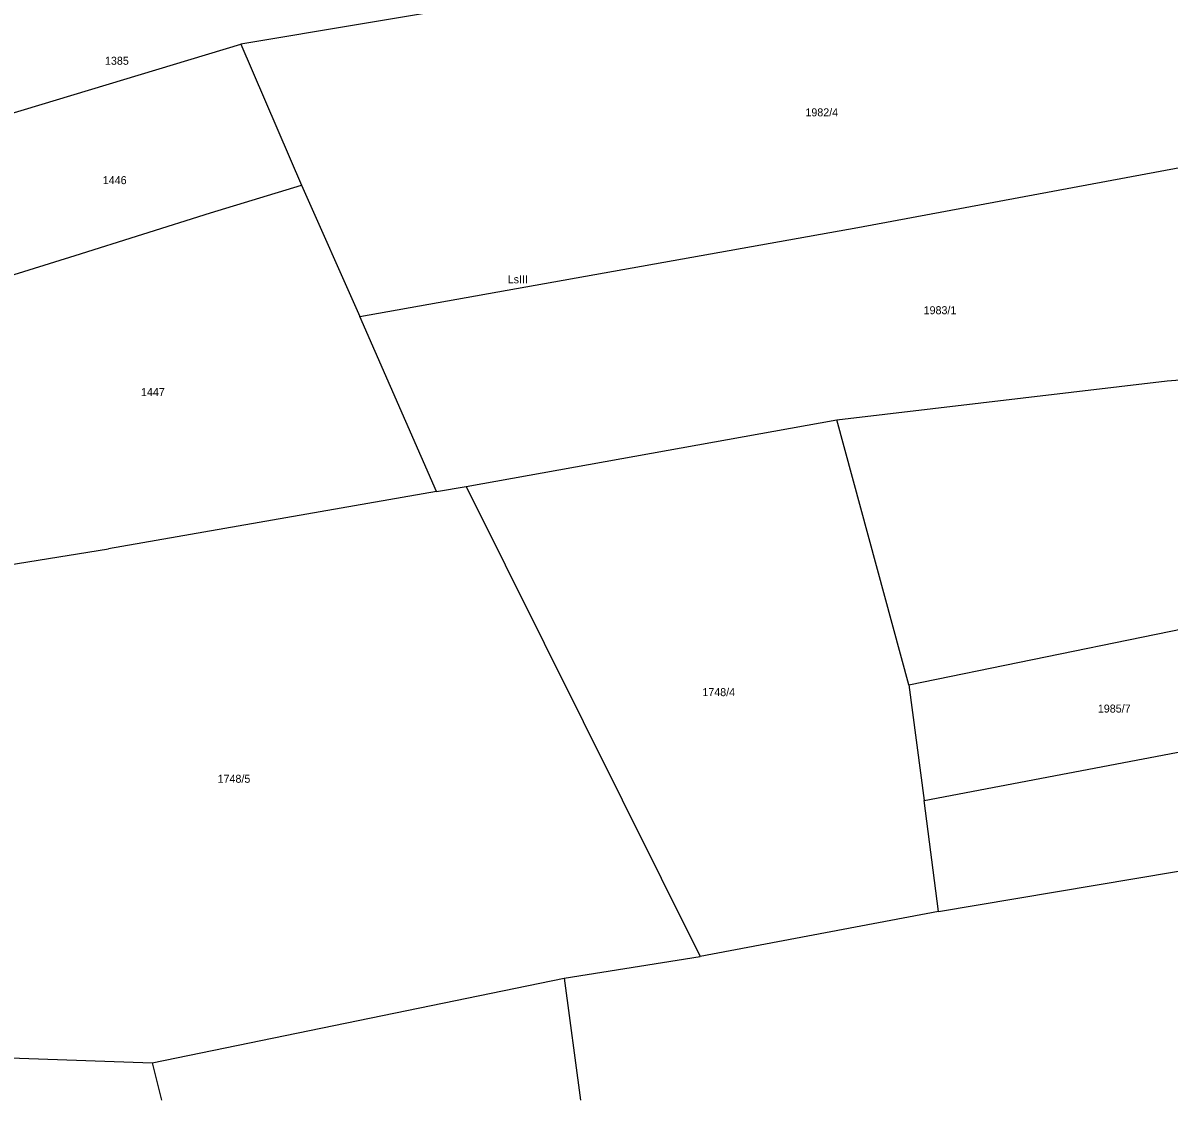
# Model space of a CAD drawing. Extents: x 7498273 to 7499989, y 5499795 to 5500810.
# Drawn here: x 7498679 to 7498893.9, y 5499795 to 5499997 of the extents above; entities that cross this region are included whole.
import ezdxf

# ---------------------------------------------------------------- set-up
doc = ezdxf.new("R2010")
doc.units = 0
for name, color, linetype in [('209-oznaczenie konturu klasyfikacyjnego', 7, 'Continuous'), ('211-numer działki ewidencyjnej', 7, 'Continuous'), ('219-działka ewidencyjna', 7, 'Continuous')]:
    doc.layers.add(name, color=color, linetype=linetype)

msp = doc.modelspace()

# ---------------------------------------------------------------- linework, layer by layer
at = {"layer": '219-działka ewidencyjna'}
for points in [[(7498788.28, 5500004.48), (7498719.91, 5499992.98)], [(7498663.32, 5499975.91), (7498719.91, 5499992.98)], [(7498719.91, 5499992.98), (7498731.28, 5499966.57)], [(7498835.55, 5499958.63), (7498922.42, 5499974.79)], [(7498714.17, 5499961.38), (7498731.28, 5499966.57)], [(7498731.28, 5499966.57), (7498742.22, 5499941.9)], [(7498688.82, 5499953.39), (7498714.17, 5499961.38)], [(7498742.22, 5499941.9), (7498835.55, 5499958.63)], [(7498671.54, 5499948.01), (7498688.82, 5499953.39)], [(7498756.55, 5499909.13), (7498742.22, 5499941.9)], [(7498893.51, 5499929.87), (7498953.54, 5499934.44)], [(7498831.64, 5499922.58), (7498893.51, 5499929.87)], [(7498762.13, 5499910.03), (7498831.64, 5499922.58)], [(7498845.11, 5499872.88), (7498831.64, 5499922.58)], [(7498756.55, 5499909.13), (7498695.1, 5499898.38)], [(7498756.55, 5499909.13), (7498762.13, 5499910.03)], [(7498762.13, 5499910.03), (7498806.01, 5499821.91)], [(7498645.79, 5499890.44), (7498695.1, 5499898.38)], [(7498845.11, 5499872.88), (7498914.67, 5499887.14)], [(7498845.11, 5499872.88), (7498847.95, 5499851.19)], [(7498847.95, 5499851.19), (7498915.97, 5499864.13)], [(7498850.67, 5499830.37), (7498847.95, 5499851.19)], [(7498850.67, 5499830.37), (7498917.24, 5499841.57)], [(7498850.67, 5499830.37), (7498806.01, 5499821.91)], [(7498780.5, 5499817.89), (7498806.01, 5499821.91)], [(7498703.29, 5499801.99), (7498780.5, 5499817.89)], [(7498780.5, 5499817.89), (7498783.561, 5499795.022)], [(7498625.04, 5499804.77), (7498703.29, 5499801.99)], [(7498703.29, 5499801.99), (7498705.018, 5499795.022)]]:
    msp.add_lwpolyline(points, dxfattribs=at)

# ---------------------------------------------------------------- texts
at = {"layer": '209-oznaczenie konturu klasyfikacyjnego'}
msp.add_text('LsIII', height=1.5, dxfattribs=at).set_placement((7498769.91, 5499948.14))
at = {"layer": '211-numer działki ewidencyjnej'}
for s, p in [('1385', (7498694.42, 5499989.12)), ('1982/4', (7498825.72, 5499979.45)), ('1446', (7498694.01, 5499966.74)), ('1983/1', (7498847.88, 5499942.35)), ('1447', (7498701.17, 5499927.01)), ('1748/4', (7498806.4, 5499870.75)), ('1985/7', (7498880.54, 5499867.67)), ('1748/5', (7498715.53, 5499854.51))]:
    msp.add_text(s, height=1.5, dxfattribs=at).set_placement(p)

doc.saveas('drawing.dxf')
